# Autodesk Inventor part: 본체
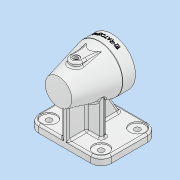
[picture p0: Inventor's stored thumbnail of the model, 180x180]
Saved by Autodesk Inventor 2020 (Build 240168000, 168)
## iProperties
Created: 2024-12
Part Number: 본체
Material: 알루미늄 6061
Document SubType Name: Modeling
Designer: shin
Density: 2.7 g/cm^3
Appearance: 알루미늄 - 평지
Mass: 739.387 g
Surface Area: 675.501 cm^2
Volume: 273.847 cm^3
Author: shin
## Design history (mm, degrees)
sketch "스케치1"
  geometry: L1 (0, 42)-(0, -42); L2 (0, -42)-(37, -42); L3 (23.5, -42)-(23.5, -24); L4 (23.5, -24)-(32.346, -24); L5 (0, -42)-(23.5, -42); L6 (32.346, -24)-(21.096, 21); L7 (15.5, 31)-(15.5, 34); L8 (15.5, 34)-(0, 34); L9 (21.096, 21)-(17.5, 21); L10 (17.5, 21)-(17.5, 31); L11 (17.5, 31)-(15.5, 31); L12 (23.5, -42)-(37, -42); L13 (21, 42)-(37, -22); L14 (0, 34)-(0, 42); L15 (0, 42)-(37, 42); L16 (37, -42)-(37, 42); L17 (21, 42)-(0, 42); L18 (37, -22)-(37, -42); 1 further point
  constraints: 36 end point, 5 perpendicular, 3 point on line, 3 vertical, 2 collinear, 2 horizontal, 1 midpoint, 1 parallel
  dimensions: "d0" = 84 distance of L2.end L15.end; "d3" = 18 distance of L3.start L3.end; "d4" = 45 distance from line of L4 L6.end; "d5" = 10 distance between parallel lines of L11 L9; "d6" = 3 distance between parallel lines of L8 L11; "d7" = 31 diameter of L7 L1; "d8" = 35 diameter of L10 L1; "d9" = 5 distance between parallel lines of L6 L13; "d10" = 47 diameter of L3 L1; "d11" = 42 diameter of L13.start L1; "d12" = 20 distance of L2.end L13.end; "d17" = 42 distance from line of L15 point (0, 0); "d18" = 74 diameter of L16 L1
revolve "회전1" sketch "스케치1" stored, may be unused: angle "d19" = 90 deg
node "작업 평면1"
sketch "스케치2"
  geometry: L1 (-57, 32)-(57, 32); L2 (57, 32)-(57, -57); L3 (57, -57)-(-57, -57); L4 (-57, -57)-(-57, 32); L5 (-21, 42)-(21, 42) reference; 1 further point
  constraints: 8 end point, 2 parallel, 1 horizontal, 1 perpendicular
  dimensions: "d21" = 89 distance of L3.end L1.start; "d22" = 114 distance of L2.end L3.end; "d23" = 99 distance between parallel lines of L5 L3; "d24" = 57 distance from line of L4 point (0, 0)
extrude "돌출1" join sketch "스케치2" distance "d25" = 12; taper "d26" = 0 deg
sketch "스케치3"
  geometry: L1 (-28, 5)-(28, 5); L2 (28, 5)-(28, -3); L3 (28, -3)-(-28, -3); L4 (-28, -3)-(-28, 5); L5 (-57, -32)-(57, -32) reference; 1 further point
  constraints: 8 end point, 2 parallel, 1 horizontal, 1 perpendicular
  dimensions: "d27" = 56 distance of L1.start L1.end; "d28" = 29 distance between parallel lines of L5 L3; "d29" = 8 distance of L3.end L1.start; "d30" = 28 distance from line of L4 point (0, 0)
extrude "돌출2" join sketch "스케치3" stored distance "d31" = 12; taper "d32" = 0 deg
sketch "스케치4"
  geometry: L1 (-70, -50)-(-37, -30.947); L2 (-37, -22)-(-37, -42) reference; L3 (-70, 32)-(-23.5, 32); L4 (-21, 42)-(-37, -22) reference; 2 further points
  constraints: 4 end point, 2 point on line, 1 horizontal
  dimensions: "d34" = 7 distance of L1.start point (-70, -57)
feature "리브1" dims "d35" = 1, "d36" = 10, "d37" = 0, "d38" = 0, "d39" = 1, "d40" = 1
feature "리브2" dims "d41" = 1, "d42" = 10, "d43" = 0, "d44" = 0, "d45" = 1, "d46" = 1
sketch "스케치6"
  geometry: L1 (57, 57)-(-57, 57) reference; 2 further points
  dimensions: "d47" = 41 horizontal distance of point (0, 0) point (-41, 41); "d49" = 16 distance from line of point (-41, 41) L1
hole "구멍1" sketch "스케치6" at (-41, 41) diameter "d50" = 9; stored, may be unused: countersink angle "d54" = 90 deg, drill point angle "d56" = 118 deg; dims "d51" = 6, "d52" = 4, "d53" = 2, "d55" = 8
sketch "스케치7"
  geometry: C1 r 4.5 at (-41, 41) reference; C2 r 12 at (-41, 41); 1 further point
  constraints: 1 centre point, 1 coincident
  dimensions: "d59" = 24 diameter of C2
fillet "모깎기1" dims "d57" = 16
fillet "모깎기2" dims "d58" = 3
extrude "돌출3" cut sketch "스케치7" distance "d60" = 2; taper "d61" = 0 deg
node "작업 평면2"
sketch "스케치8"
  geometry: L1 (-37, -42)-(37, -42) reference; L2 (-37, -22)-(37, -22) reference; L3 (10, 14)-(10, -22); L4 (-10, 14)-(-10, -22); A1 r 10 centre (0, 14) between (10, 14) and (-10, 14); 3 further points
  constraints: 4 end point, 2 point on circle, 2 point on line, 2 tangent, 1 centre point, 1 perpendicular, 1 vertical, 1 vertical alignment
  dimensions: "d65" = 20 diameter of A1; "d66" = 56 distance from line of L1 A1.centre
extrude "돌출4" join sketch "스케치8" stored distance "d67" = 2; taper "d68" = 0 deg
sketch "스케치9"
  geometry: C1 r 5 at (0, -14); A1 r 10 centre (0, -14) between (-10, -14) and (10, -14) reference; 1 further point
  constraints: 1 centre point, 1 coincident
  dimensions: "d69" = 10 diameter of C1
extrude "돌출5" cut sketch "스케치9" distance "d70" = 1; taper "d71" = 0 deg
sketch "스케치10"
  geometry: C1 r 5 at (0, 0) reference; C2 r 3 at (0, 0); 1 further point
  constraints: 1 centre point, 1 coincident
  dimensions: "d72" = 6 diameter of C2
extrude "돌출6" cut sketch "스케치10" stored distance "d73" = 1; taper "d74" = 0 deg
feature "스레드1" dims "d75" = 4.75, "d76" = 0
node "작업 평면3"
sketch "스케치11"
  geometry: L1 (-37, -10)-(37, -10) reference; 2 further points
  constraints: 1 vertical alignment, 1 other
  dimensions: "d83" = 9 distance from line of L1 point (0, -1)
feature "엠보싱1" sketch "스케치11" dims "d20" = -82, "d84" = 0.5, "d85" = 0
fillet "모깎기3" dims "d86" = 3
fillet "모깎기4" dims "d87" = 3
fillet "모깎기5" dims "d88" = 3
fillet "모깎기6" dims "d89" = 3
fillet "모깎기7" dims "d90" = 3
fillet "모깎기8" dims "d91" = 3
fillet "모깎기9" dims "d92" = 0.3
fillet "모깎기10" dims "d93" = 3
chamfer "모따기1" distance "d94" = 1; stored, may be unused: second distance "d95" = 2, angle "d96" = 45 deg
chamfer "모따기2" distance "d97" = 1; stored, may be unused: second distance "d98" = 2, angle "d99" = 45 deg
fillet "모깎기11" dims "d100" = 5
sketch "스케치12" dims "d101" = 57
  geometry: 3 further points
  constraints: 2 vertical alignment, 1 coincident, 2 other
hole "구멍2" sketch "스케치12" at (0, 28.5) diameter "d102" = 3.242; stored, may be unused: countersink angle "d106" = 90 deg, drill point angle "d108" = 118 deg; dims "d103" = 8, "d104" = 4, "d105" = 2, "d107" = 10
node "솔리드1"
pattern_linear "직사각형 패턴1" dims "d79" = 82, "d82" = 57
pattern_circular "원형 패턴1" dims angle "d110" = 360 deg
feature "A9D066F2-1C7D-4E18-AEED-F7BC21143FA4" dims "d102" = 3.242, "d103" = 8, "d104" = 4, "d105" = 2, "d106" = 90 deg, "d107" = 10, "d108" = 118 deg
other parameters: "d62" = -115
